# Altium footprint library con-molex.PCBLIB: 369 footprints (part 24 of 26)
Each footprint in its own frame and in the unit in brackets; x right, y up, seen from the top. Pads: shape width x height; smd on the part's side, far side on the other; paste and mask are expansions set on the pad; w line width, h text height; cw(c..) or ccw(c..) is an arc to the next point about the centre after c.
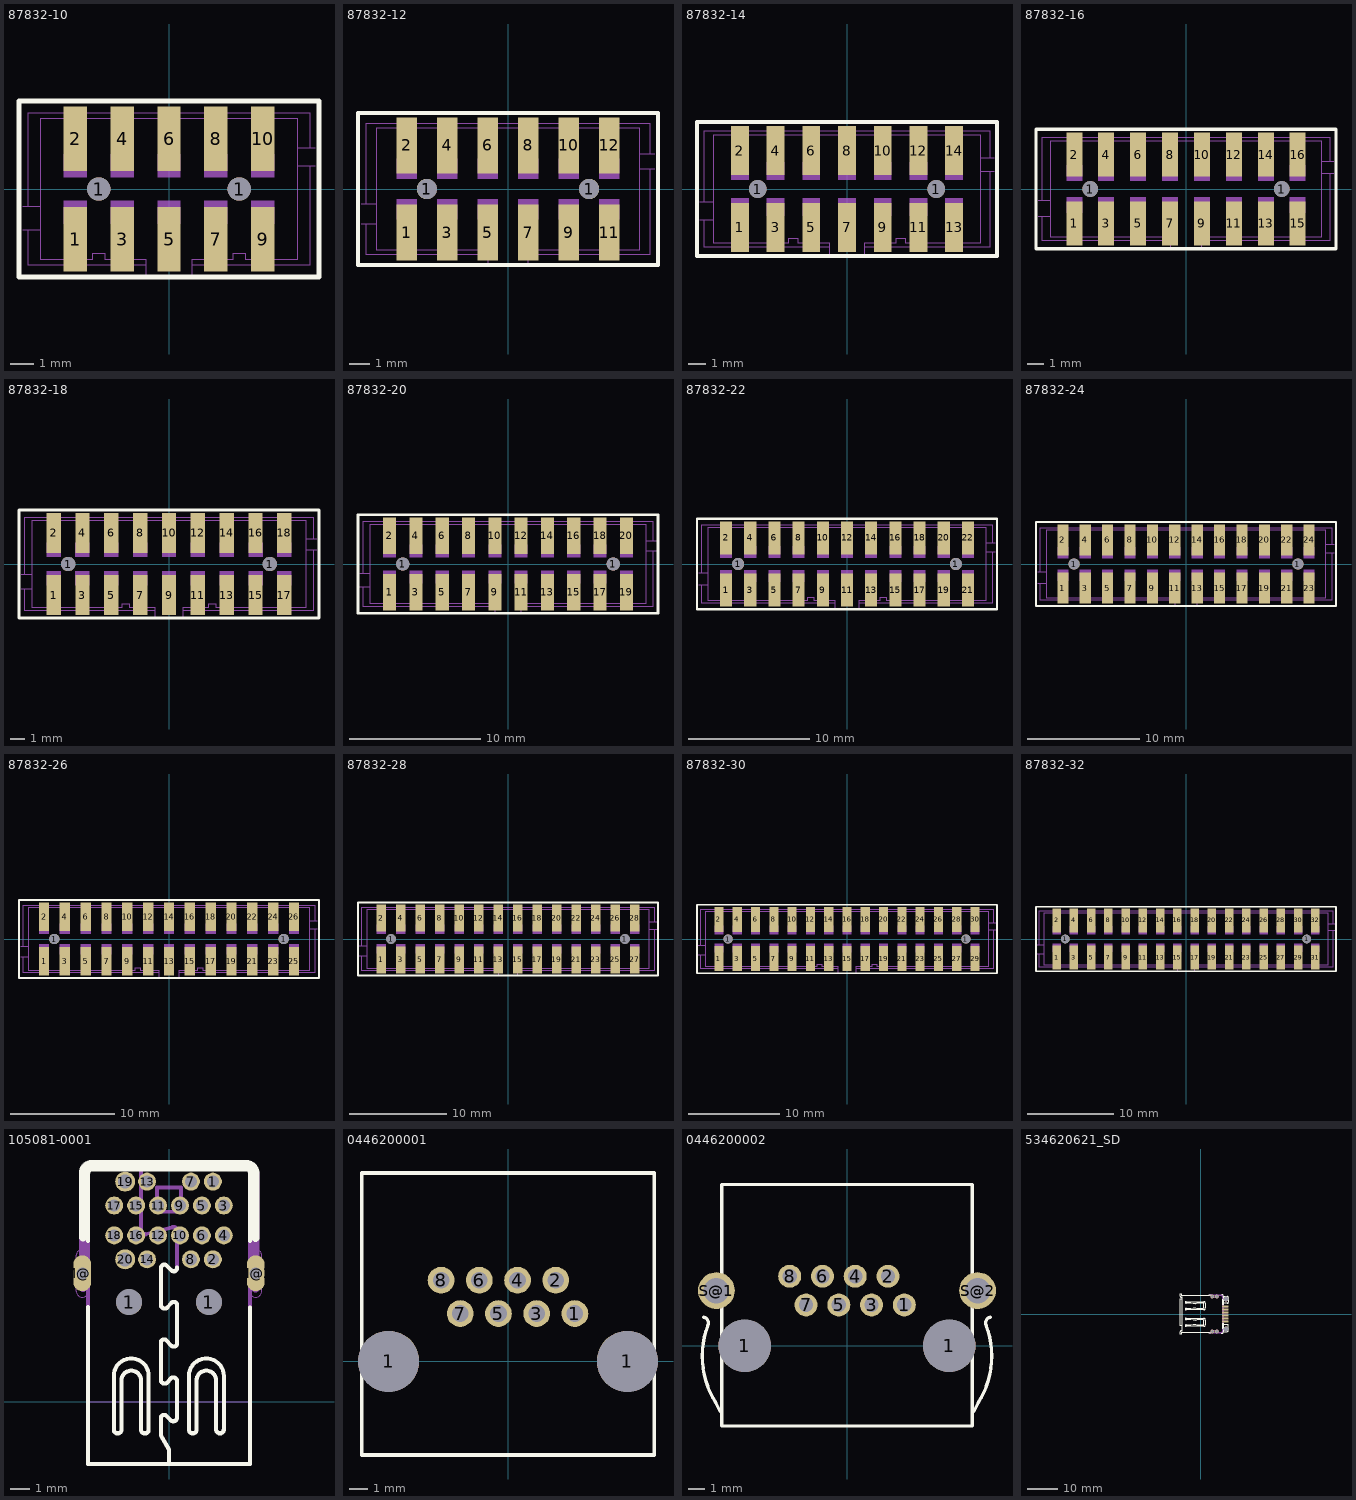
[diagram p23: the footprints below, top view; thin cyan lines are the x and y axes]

## 87832-10 [mm]
pads (12):
  rect 1x2.75 smd: 1(-4,-2.15) 2(-4,2.15) 3(-2,-2.15) 4(-2,2.15) 5(0,-2.15) 6(0,2.15) 7(2,-2.15) 8(2,2.15) 9(4,-2.15) 10(4,2.15)
  round 1 hole 1: 1(-3,0) 1(3,0)
Top Overlay:
  lines w0.203: -6.4,-3.75 6.4,-3.75 6.4,3.75 -6.4,3.75 -6.4,-3.75
Mechanical 16:
  rectangle: -4.5,0.5 -3.5,1.5
  rectangle: -2.5,0.5 -1.5,1.5
  rectangle: -0.5,0.5 0.5,1.5
  rectangle: 1.5,0.5 2.5,1.5
  rectangle: -4.5,-1.5 -3.5,-0.5
  rectangle: -2.5,-1.5 -1.5,-0.5
  rectangle: -0.5,-1.5 0.5,-0.5
  rectangle: 1.5,-1.5 2.5,-0.5
  rectangle: 3.5,0.5 4.5,1.5
  rectangle: 3.5,-1.5 4.5,-0.5
  lines w0.051: -6.25,-1.75 -6,-1.75 ; -6.25,-0.75 -6,-0.75 ; -1,-3.75 -1,-3.25 ; 1,-3.75 1,-3.25 ; 6.25,1 6,1 ; 6.25,1.75 6,1.75 ; -6,-1.75 -5.5,-1.75 ; -6,-1.75 -6,-3.25 -1,-3.25 ; -6,-0.75 -5.5,-0.75 ; -6,-0.75 -6,3.25 6,3.25 6,1.75 ; -5.5,-1.75 -5.5,-0.75 ; -5.5,-1.75 -5.5,-3 -3.25,-3 -3.25,-2.75 -2.75,-2.75 -2.75,-3 -1,-3 -1,-3.25 ; -5.5,-0.75 -5.5,3 -4.25,3 -4.25,2.75 -3.75,2.75 -3.75,3 -2.25,3 -2.25,2.75 -1.75,2.75 -1.75,3 -0.25,3 -0.25,2.75 0.25,2.75 0.25,3 1.75,3 1.75,2.75 2.25,2.75 2.25,3 3.75,3 3.75,2.75 4.25,2.75 4.25,3 5.5,3 5.5,1.75 ; 1,-3.25 1,-3 2.75,-3 2.75,-2.75 3.25,-2.75 3.25,-3 5.5,-3 5.5,1 ; 1,-3.25 6,-3.25 6,1 ; 5.5,1 5.5,1.75 ; 5.5,1 6,1 ; 5.5,1.75 6,1.75
  text "1" at -5.25,-2.75 h0.94

## 87832-12 [mm]
pads (14):
  rect 1x2.75 smd: 1(-5,-2.15) 2(-5,2.15) 3(-3,-2.15) 4(-3,2.15) 5(-1,-2.15) 6(-1,2.15) 7(1,-2.15) 8(1,2.15) 9(3,-2.15) 10(3,2.15) 11(5,-2.15) 12(5,2.15)
  round 1 hole 1: 1(-4,0) 1(4,0)
Top Overlay:
  lines w0.203: -7.4,-3.75 7.4,-3.75 7.4,3.75 -7.4,3.75 -7.4,-3.75
Mechanical 16:
  rectangle: -5.5,0.5 -4.5,1.5
  rectangle: -3.5,0.5 -2.5,1.5
  rectangle: -1.5,0.5 -0.5,1.5
  rectangle: 0.5,0.5 1.5,1.5
  rectangle: -5.5,-1.5 -4.5,-0.5
  rectangle: -3.5,-1.5 -2.5,-0.5
  rectangle: -1.5,-1.5 -0.5,-0.5
  rectangle: 0.5,-1.5 1.5,-0.5
  rectangle: 2.5,0.5 3.5,1.5
  rectangle: 2.5,-1.5 3.5,-0.5
  rectangle: 4.5,0.5 5.5,1.5
  rectangle: 4.5,-1.5 5.5,-0.5
  lines w0.051: -7.25,-1.75 -7,-1.75 ; -7.25,-0.75 -7,-0.75 ; -1,-3.75 -1,-3.25 ; 1,-3.75 1,-3.25 ; 7.25,1 7,1 ; 7.25,1.75 7,1.75 ; -7,-1.75 -6.5,-1.75 ; -7,-1.75 -7,-3.25 -1,-3.25 ; -7,-0.75 -6.5,-0.75 ; -7,-0.75 -7,3.25 7,3.25 7,1.75 ; -6.5,-1.75 -6.5,-0.75 ; -6.5,-1.75 -6.5,-3 -3.25,-3 -3.25,-2.75 -2.75,-2.75 -2.75,-3 -1,-3 -1,-3.25 ; -6.5,-0.75 -6.5,3 -5.25,3 -5.25,2.75 -4.75,2.75 -4.75,3 -3.25,3 -3.25,2.75 -2.75,2.75 -2.75,3 -1.25,3 -1.25,2.75 -0.75,2.75 -0.75,3 0.75,3 0.75,2.75 1.25,2.75 1.25,3 2.75,3 2.75,2.75 3.25,2.75 3.25,3 4.75,3 4.75,2.75 5.25,2.75 5.25,3 6.5,3 6.5,1.75 ; 1,-3.25 1,-3 2.75,-3 2.75,-2.75 3.25,-2.75 3.25,-3 6.5,-3 6.5,1 ; 1,-3.25 7,-3.25 7,1 ; 6.5,1 6.5,1.75 ; 6.5,1 7,1 ; 6.5,1.75 7,1.75
  text "1" at -6.25,-2.75 h0.94

## 87832-14 [mm]
pads (16):
  rect 1x2.75 smd: 1(-6,-2.15) 2(-6,2.15) 3(-4,-2.15) 4(-4,2.15) 5(-2,-2.15) 6(-2,2.15) 7(0,-2.15) 8(0,2.15) 9(2,-2.15) 10(2,2.15) 11(4,-2.15) 12(4,2.15) 13(6,-2.15) 14(6,2.15)
  round 1 hole 1: 1(-5,0) 1(5,0)
Top Overlay:
  lines w0.203: -8.4,-3.75 8.4,-3.75 8.4,3.75 -8.4,3.75 -8.4,-3.75
Mechanical 16:
  rectangle: -6.5,0.5 -5.5,1.5
  rectangle: -4.5,0.5 -3.5,1.5
  rectangle: -2.5,0.5 -1.5,1.5
  rectangle: -0.5,0.5 0.5,1.5
  rectangle: -6.5,-1.5 -5.5,-0.5
  rectangle: -4.5,-1.5 -3.5,-0.5
  rectangle: -2.5,-1.5 -1.5,-0.5
  rectangle: -0.5,-1.5 0.5,-0.5
  rectangle: 1.5,0.5 2.5,1.5
  rectangle: 1.5,-1.5 2.5,-0.5
  rectangle: 3.5,0.5 4.5,1.5
  rectangle: 3.5,-1.5 4.5,-0.5
  rectangle: 5.5,0.5 6.5,1.5
  rectangle: 5.5,-1.5 6.5,-0.5
  lines w0.051: -8.25,-1.75 -8,-1.75 ; -8.25,-0.75 -8,-0.75 ; -1,-3.75 -1,-3.25 ; 1,-3.75 1,-3.25 ; 8.25,1 8,1 ; 8.25,1.75 8,1.75 ; -8,-1.75 -7.5,-1.75 ; -8,-1.75 -8,-3.25 -1,-3.25 ; -8,-0.75 -7.5,-0.75 ; -8,-0.75 -8,3.25 8,3.25 8,1.75 ; -7.5,-1.75 -7.5,-0.75 ; -7.5,-1.75 -7.5,-3 -3.25,-3 -3.25,-2.75 -2.75,-2.75 -2.75,-3 -1,-3 -1,-3.25 ; -7.5,-0.75 -7.5,3 -6.25,3 -6.25,2.75 -5.75,2.75 -5.75,3 -4.25,3 -4.25,2.75 -3.75,2.75 -3.75,3 -2.25,3 -2.25,2.75 -1.75,2.75 -1.75,3 -0.25,3 -0.25,2.75 0.25,2.75 0.25,3 1.75,3 1.75,2.75 2.25,2.75 2.25,3 3.75,3 3.75,2.75 4.25,2.75 4.25,3 5.75,3 5.75,2.75 6.25,2.75 6.25,3 7.5,3 7.5,1.75 ; 1,-3.25 1,-3 2.75,-3 2.75,-2.75 3.25,-2.75 3.25,-3 7.5,-3 7.5,1 ; 1,-3.25 8,-3.25 8,1 ; 7.5,1 7.5,1.75 ; 7.5,1 8,1 ; 7.5,1.75 8,1.75
  text "1" at -7.25,-2.75 h0.94

## 87832-16 [mm]
pads (18):
  rect 1x2.75 smd: 1(-7,-2.15) 2(-7,2.15) 3(-5,-2.15) 4(-5,2.15) 5(-3,-2.15) 6(-3,2.15) 7(-1,-2.15) 8(-1,2.15) 9(1,-2.15) 10(1,2.15) 11(3,-2.15) 12(3,2.15) 13(5,-2.15) 14(5,2.15) 15(7,-2.15) 16(7,2.15)
  round 1 hole 1: 1(-6,0) 1(6,0)
Top Overlay:
  lines w0.203: -9.4,-3.75 9.4,-3.75 9.4,3.75 -9.4,3.75 -9.4,-3.75
Mechanical 16:
  rectangle: -7.5,0.5 -6.5,1.5
  rectangle: -5.5,0.5 -4.5,1.5
  rectangle: -3.5,0.5 -2.5,1.5
  rectangle: -1.5,0.5 -0.5,1.5
  rectangle: -7.5,-1.5 -6.5,-0.5
  rectangle: -5.5,-1.5 -4.5,-0.5
  rectangle: -3.5,-1.5 -2.5,-0.5
  rectangle: -1.5,-1.5 -0.5,-0.5
  rectangle: 0.5,0.5 1.5,1.5
  rectangle: 0.5,-1.5 1.5,-0.5
  rectangle: 2.5,0.5 3.5,1.5
  rectangle: 2.5,-1.5 3.5,-0.5
  rectangle: 4.5,0.5 5.5,1.5
  rectangle: 4.5,-1.5 5.5,-0.5
  rectangle: 6.5,0.5 7.5,1.5
  rectangle: 6.5,-1.5 7.5,-0.5
  lines w0.051: -9.25,-1.75 -9,-1.75 ; -9.25,-0.75 -9,-0.75 ; -1,-3.75 -1,-3.25 ; 1,-3.75 1,-3.25 ; 9.25,1 9,1 ; 9.25,1.75 9,1.75 ; -9,-1.75 -8.5,-1.75 ; -9,-1.75 -9,-3.25 -1,-3.25 ; -9,-0.75 -8.5,-0.75 ; -9,-0.75 -9,3.25 9,3.25 9,1.75 ; -8.5,-1.75 -8.5,-0.75 ; -8.5,-1.75 -8.5,-3 -3.25,-3 -3.25,-2.75 -2.75,-2.75 -2.75,-3 -1,-3 -1,-3.25 ; -8.5,-0.75 -8.5,3 -7.25,3 -7.25,2.75 -6.75,2.75 -6.75,3 -5.25,3 -5.25,2.75 -4.75,2.75 -4.75,3 -3.25,3 -3.25,2.75 -2.75,2.75 -2.75,3 -1.25,3 -1.25,2.75 -0.75,2.75 -0.75,3 0.75,3 0.75,2.75 1.25,2.75 1.25,3 2.75,3 2.75,2.75 3.25,2.75 3.25,3 4.75,3 4.75,2.75 5.25,2.75 5.25,3 6.75,3 6.75,2.75 7.25,2.75 7.25,3 8.5,3 8.5,1.75 ; 1,-3.25 1,-3 2.75,-3 2.75,-2.75 3.25,-2.75 3.25,-3 8.5,-3 8.5,1 ; 1,-3.25 9,-3.25 9,1 ; 8.5,1 8.5,1.75 ; 8.5,1 9,1 ; 8.5,1.75 9,1.75
  text "1" at -8.25,-2.75 h0.94

## 87832-18 [mm]
pads (20):
  rect 1x2.75 smd: 1(-8,-2.15) 2(-8,2.15) 3(-6,-2.15) 4(-6,2.15) 5(-4,-2.15) 6(-4,2.15) 7(-2,-2.15) 8(-2,2.15) 9(0,-2.15) 10(0,2.15) 11(2,-2.15) 12(2,2.15) 13(4,-2.15) 14(4,2.15) 15(6,-2.15) 16(6,2.15) 17(8,-2.15) 18(8,2.15)
  round 1 hole 1: 1(-7,0) 1(7,0)
Top Overlay:
  lines w0.203: -10.4,-3.75 10.4,-3.75 10.4,3.75 -10.4,3.75 -10.4,-3.75
Mechanical 16:
  rectangle: -8.5,0.5 -7.5,1.5
  rectangle: -6.5,0.5 -5.5,1.5
  rectangle: -4.5,0.5 -3.5,1.5
  rectangle: -2.5,0.5 -1.5,1.5
  rectangle: -8.5,-1.5 -7.5,-0.5
  rectangle: -6.5,-1.5 -5.5,-0.5
  rectangle: -4.5,-1.5 -3.5,-0.5
  rectangle: -2.5,-1.5 -1.5,-0.5
  rectangle: -0.5,0.5 0.5,1.5
  rectangle: -0.5,-1.5 0.5,-0.5
  rectangle: 1.5,0.5 2.5,1.5
  rectangle: 1.5,-1.5 2.5,-0.5
  rectangle: 3.5,0.5 4.5,1.5
  rectangle: 3.5,-1.5 4.5,-0.5
  rectangle: 5.5,0.5 6.5,1.5
  rectangle: 5.5,-1.5 6.5,-0.5
  rectangle: 7.5,0.5 8.5,1.5
  rectangle: 7.5,-1.5 8.5,-0.5
  lines w0.051: -10.25,-1.75 -10,-1.75 ; -10.25,-0.75 -10,-0.75 ; -1,-3.75 -1,-3.25 ; 1,-3.75 1,-3.25 ; 10.25,1 10,1 ; 10.25,1.75 10,1.75 ; -10,-1.75 -9.5,-1.75 ; -10,-1.75 -10,-3.25 -1,-3.25 ; -10,-0.75 -9.5,-0.75 ; -10,-0.75 -10,3.25 10,3.25 10,1.75 ; -9.5,-1.75 -9.5,-0.75 ; -9.5,-1.75 -9.5,-3 -3.25,-3 -3.25,-2.75 -2.75,-2.75 -2.75,-3 -1,-3 -1,-3.25 ; -9.5,-0.75 -9.5,3 -8.25,3 -8.25,2.75 -7.75,2.75 -7.75,3 -6.25,3 -6.25,2.75 -5.75,2.75 -5.75,3 -4.25,3 -4.25,2.75 -3.75,2.75 -3.75,3 -2.25,3 -2.25,2.75 -1.75,2.75 -1.75,3 -0.25,3 -0.25,2.75 0.25,2.75 0.25,3 1.75,3 1.75,2.75 2.25,2.75 2.25,3 3.75,3 3.75,2.75 4.25,2.75 4.25,3 5.75,3 5.75,2.75 6.25,2.75 6.25,3 7.75,3 7.75,2.75 8.25,2.75 8.25,3 9.5,3 9.5,1.75 ; 1,-3.25 1,-3 2.75,-3 2.75,-2.75 3.25,-2.75 3.25,-3 9.5,-3 9.5,1 ; 1,-3.25 10,-3.25 10,1 ; 9.5,1 9.5,1.75 ; 9.5,1 10,1 ; 9.5,1.75 10,1.75
  text "1" at -9.25,-2.75 h0.94

## 87832-20 [mm]
pads (22):
  rect 1x2.75 smd: 1(-9,-2.15) 2(-9,2.15) 3(-7,-2.15) 4(-7,2.15) 5(-5,-2.15) 6(-5,2.15) 7(-3,-2.15) 8(-3,2.15) 9(-1,-2.15) 10(-1,2.15) 11(1,-2.15) 12(1,2.15) 13(3,-2.15) 14(3,2.15) 15(5,-2.15) 16(5,2.15) 17(7,-2.15) 18(7,2.15) 19(9,-2.15) 20(9,2.15)
  round 1 hole 1: 1(-8,0) 1(8,0)
Top Overlay:
  lines w0.203: -11.4,-3.75 11.4,-3.75 11.4,3.75 -11.4,3.75 -11.4,-3.75
Mechanical 16:
  rectangle: -9.5,0.5 -8.5,1.5
  rectangle: -7.5,0.5 -6.5,1.5
  rectangle: -5.5,0.5 -4.5,1.5
  rectangle: -3.5,0.5 -2.5,1.5
  rectangle: -9.5,-1.5 -8.5,-0.5
  rectangle: -7.5,-1.5 -6.5,-0.5
  rectangle: -5.5,-1.5 -4.5,-0.5
  rectangle: -3.5,-1.5 -2.5,-0.5
  rectangle: -1.5,0.5 -0.5,1.5
  rectangle: -1.5,-1.5 -0.5,-0.5
  rectangle: 0.5,0.5 1.5,1.5
  rectangle: 0.5,-1.5 1.5,-0.5
  rectangle: 2.5,0.5 3.5,1.5
  rectangle: 2.5,-1.5 3.5,-0.5
  rectangle: 4.5,0.5 5.5,1.5
  rectangle: 4.5,-1.5 5.5,-0.5
  rectangle: 6.5,0.5 7.5,1.5
  rectangle: 6.5,-1.5 7.5,-0.5
  rectangle: 8.5,0.5 9.5,1.5
  rectangle: 8.5,-1.5 9.5,-0.5
  lines w0.051: -11.25,-1.75 -11,-1.75 ; -11.25,-0.75 -11,-0.75 ; -1,-3.75 -1,-3.25 ; 1,-3.75 1,-3.25 ; 11.25,1 11,1 ; 11.25,1.75 11,1.75 ; -11,-1.75 -10.5,-1.75 ; -11,-1.75 -11,-3.25 -1,-3.25 ; -11,-0.75 -10.5,-0.75 ; -11,-0.75 -11,3.25 11,3.25 11,1.75 ; -10.5,-1.75 -10.5,-0.75 ; -10.5,-1.75 -10.5,-3 -3.25,-3 -3.25,-2.75 -2.75,-2.75 -2.75,-3 -1,-3 -1,-3.25 ; -10.5,-0.75 -10.5,3 -9.25,3 -9.25,2.75 -8.75,2.75 -8.75,3 -7.25,3 -7.25,2.75 -6.75,2.75 -6.75,3 -5.25,3 -5.25,2.75 -4.75,2.75 -4.75,3 -3.25,3 -3.25,2.75 -2.75,2.75 -2.75,3 -1.25,3 -1.25,2.75 -0.75,2.75 -0.75,3 0.75,3 0.75,2.75 1.25,2.75 1.25,3 2.75,3 2.75,2.75 3.25,2.75 3.25,3 4.75,3 4.75,2.75 5.25,2.75 5.25,3 6.75,3 6.75,2.75 7.25,2.75 7.25,3 8.75,3 8.75,2.75 9.25,2.75 9.25,3 10.5,3 10.5,1.75 ; 1,-3.25 1,-3 2.75,-3 2.75,-2.75 3.25,-2.75 3.25,-3 10.5,-3 10.5,1 ; 1,-3.25 11,-3.25 11,1 ; 10.5,1 10.5,1.75 ; 10.5,1 11,1 ; 10.5,1.75 11,1.75
  text "1" at -10.25,-2.75 h0.94

## 87832-22 [mm]
pads (24):
  rect 1x2.75 smd: 1(-10,-2.15) 2(-10,2.15) 3(-8,-2.15) 4(-8,2.15) 5(-6,-2.15) 6(-6,2.15) 7(-4,-2.15) 8(-4,2.15) 9(-2,-2.15) 10(-2,2.15) 11(0,-2.15) 12(0,2.15) 13(2,-2.15) 14(2,2.15) 15(4,-2.15) 16(4,2.15) 17(6,-2.15) 18(6,2.15) 19(8,-2.15) 20(8,2.15) 21(10,-2.15) 22(10,2.15)
  round 1 hole 1: 1(-9,0) 1(9,0)
Top Overlay:
  lines w0.203: -12.4,-3.75 12.4,-3.75 12.4,3.75 -12.4,3.75 -12.4,-3.75
Mechanical 16:
  rectangle: -10.5,0.5 -9.5,1.5
  rectangle: -8.5,0.5 -7.5,1.5
  rectangle: -6.5,0.5 -5.5,1.5
  rectangle: -4.5,0.5 -3.5,1.5
  rectangle: -10.5,-1.5 -9.5,-0.5
  rectangle: -8.5,-1.5 -7.5,-0.5
  rectangle: -6.5,-1.5 -5.5,-0.5
  rectangle: -4.5,-1.5 -3.5,-0.5
  rectangle: -2.5,0.5 -1.5,1.5
  rectangle: -2.5,-1.5 -1.5,-0.5
  rectangle: -0.5,0.5 0.5,1.5
  rectangle: -0.5,-1.5 0.5,-0.5
  rectangle: 1.5,0.5 2.5,1.5
  rectangle: 1.5,-1.5 2.5,-0.5
  rectangle: 3.5,0.5 4.5,1.5
  rectangle: 3.5,-1.5 4.5,-0.5
  rectangle: 5.5,0.5 6.5,1.5
  rectangle: 5.5,-1.5 6.5,-0.5
  rectangle: 7.5,0.5 8.5,1.5
  rectangle: 7.5,-1.5 8.5,-0.5
  rectangle: 9.5,0.5 10.5,1.5
  rectangle: 9.5,-1.5 10.5,-0.5
  lines w0.051: -12.25,-1.75 -12,-1.75 ; -12.25,-0.75 -12,-0.75 ; -1,-3.75 -1,-3.25 ; 1,-3.75 1,-3.25 ; 12.25,1 12,1 ; 12.25,1.75 12,1.75 ; -12,-1.75 -11.5,-1.75 ; -12,-1.75 -12,-3.25 -1,-3.25 ; -12,-0.75 -11.5,-0.75 ; -12,-0.75 -12,3.25 12,3.25 12,1.75 ; -11.5,-1.75 -11.5,-0.75 ; -11.5,-1.75 -11.5,-3 -3.25,-3 -3.25,-2.75 -2.75,-2.75 -2.75,-3 -1,-3 -1,-3.25 ; -11.5,-0.75 -11.5,3 -10.25,3 -10.25,2.75 -9.75,2.75 -9.75,3 -8.25,3 -8.25,2.75 -7.75,2.75 -7.75,3 -6.25,3 -6.25,2.75 -5.75,2.75 -5.75,3 -4.25,3 -4.25,2.75 -3.75,2.75 -3.75,3 -2.25,3 -2.25,2.75 -1.75,2.75 -1.75,3 -0.25,3 -0.25,2.75 0.25,2.75 0.25,3 1.75,3 1.75,2.75 2.25,2.75 2.25,3 3.75,3 3.75,2.75 4.25,2.75 4.25,3 5.75,3 5.75,2.75 6.25,2.75 6.25,3 7.75,3 7.75,2.75 8.25,2.75 8.25,3 9.75,3 9.75,2.75 10.25,2.75 10.25,3 11.5,3 11.5,1.75 ; 1,-3.25 1,-3 2.75,-3 2.75,-2.75 3.25,-2.75 3.25,-3 11.5,-3 11.5,1 ; 1,-3.25 12,-3.25 12,1 ; 11.5,1 11.5,1.75 ; 11.5,1 12,1 ; 11.5,1.75 12,1.75
  text "1" at -11.25,-2.75 h0.94

## 87832-24 [mm]
pads (26):
  rect 1x2.75 smd: 1(-11,-2.15) 2(-11,2.15) 3(-9,-2.15) 4(-9,2.15) 5(-7,-2.15) 6(-7,2.15) 7(-5,-2.15) 8(-5,2.15) 9(-3,-2.15) 10(-3,2.15) 11(-1,-2.15) 12(-1,2.15) 13(1,-2.15) 14(1,2.15) 15(3,-2.15) 16(3,2.15) 17(5,-2.15) 18(5,2.15) 19(7,-2.15) 20(7,2.15) 21(9,-2.15) 22(9,2.15) 23(11,-2.15) 24(11,2.15)
  round 1 hole 1: 1(-10,0) 1(10,0)
Top Overlay:
  lines w0.203: -13.4,-3.75 13.4,-3.75 13.4,3.75 -13.4,3.75 -13.4,-3.75
Mechanical 16:
  rectangle: -11.5,0.5 -10.5,1.5
  rectangle: -9.5,0.5 -8.5,1.5
  rectangle: -7.5,0.5 -6.5,1.5
  rectangle: -5.5,0.5 -4.5,1.5
  rectangle: -11.5,-1.5 -10.5,-0.5
  rectangle: -9.5,-1.5 -8.5,-0.5
  rectangle: -7.5,-1.5 -6.5,-0.5
  rectangle: -5.5,-1.5 -4.5,-0.5
  rectangle: -3.5,0.5 -2.5,1.5
  rectangle: -3.5,-1.5 -2.5,-0.5
  rectangle: -1.5,0.5 -0.5,1.5
  rectangle: -1.5,-1.5 -0.5,-0.5
  rectangle: 0.5,0.5 1.5,1.5
  rectangle: 0.5,-1.5 1.5,-0.5
  rectangle: 2.5,0.5 3.5,1.5
  rectangle: 2.5,-1.5 3.5,-0.5
  rectangle: 4.5,0.5 5.5,1.5
  rectangle: 4.5,-1.5 5.5,-0.5
  rectangle: 6.5,0.5 7.5,1.5
  rectangle: 6.5,-1.5 7.5,-0.5
  rectangle: 8.5,0.5 9.5,1.5
  rectangle: 8.5,-1.5 9.5,-0.5
  rectangle: 10.5,0.5 11.5,1.5
  rectangle: 10.5,-1.5 11.5,-0.5
  lines w0.051: -13.25,-1.75 -13,-1.75 ; -13.25,-0.75 -13,-0.75 ; -1,-3.75 -1,-3.25 ; 1,-3.75 1,-3.25 ; 13.25,1 13,1 ; 13.25,1.75 13,1.75 ; -13,-1.75 -12.5,-1.75 ; -13,-1.75 -13,-3.25 -1,-3.25 ; -13,-0.75 -12.5,-0.75 ; -13,-0.75 -13,3.25 13,3.25 13,1.75 ; -12.5,-1.75 -12.5,-0.75 ; -12.5,-1.75 -12.5,-3 -3.25,-3 -3.25,-2.75 -2.75,-2.75 -2.75,-3 -1,-3 -1,-3.25 ; -12.5,-0.75 -12.5,3 -11.25,3 -11.25,2.75 -10.75,2.75 -10.75,3 -9.25,3 -9.25,2.75 -8.75,2.75 -8.75,3 -7.25,3 -7.25,2.75 -6.75,2.75 -6.75,3 -5.25,3 -5.25,2.75 -4.75,2.75 -4.75,3 -3.25,3 -3.25,2.75 -2.75,2.75 -2.75,3 -1.25,3 -1.25,2.75 -0.75,2.75 -0.75,3 0.75,3 0.75,2.75 1.25,2.75 1.25,3 2.75,3 2.75,2.75 3.25,2.75 3.25,3 4.75,3 4.75,2.75 5.25,2.75 5.25,3 6.75,3 6.75,2.75 7.25,2.75 7.25,3 8.75,3 8.75,2.75 9.25,2.75 9.25,3 10.75,3 10.75,2.75 11.25,2.75 11.25,3 12.5,3 12.5,1.75 ; 1,-3.25 1,-3 2.75,-3 2.75,-2.75 3.25,-2.75 3.25,-3 12.5,-3 12.5,1 ; 1,-3.25 13,-3.25 13,1 ; 12.5,1 12.5,1.75 ; 12.5,1 13,1 ; 12.5,1.75 13,1.75
  text "1" at -12.25,-2.75 h0.94

## 87832-26 [mm]
pads (28):
  rect 1x2.75 smd: 1(-12,-2.15) 2(-12,2.15) 3(-10,-2.15) 4(-10,2.15) 5(-8,-2.15) 6(-8,2.15) 7(-6,-2.15) 8(-6,2.15) 9(-4,-2.15) 10(-4,2.15) 11(-2,-2.15) 12(-2,2.15) 13(0,-2.15) 14(0,2.15) 15(2,-2.15) 16(2,2.15) 17(4,-2.15) 18(4,2.15) 19(6,-2.15) 20(6,2.15) 21(8,-2.15) 22(8,2.15) 23(10,-2.15) 24(10,2.15) 25(12,-2.15) 26(12,2.15)
  round 1 hole 1: 1(-11,0) 1(11,0)
Top Overlay:
  lines w0.203: -14.4,-3.75 14.4,-3.75 14.4,3.75 -14.4,3.75 -14.4,-3.75
Mechanical 16:
  rectangle: -12.5,0.5 -11.5,1.5
  rectangle: -10.5,0.5 -9.5,1.5
  rectangle: -8.5,0.5 -7.5,1.5
  rectangle: -6.5,0.5 -5.5,1.5
  rectangle: -12.5,-1.5 -11.5,-0.5
  rectangle: -10.5,-1.5 -9.5,-0.5
  rectangle: -8.5,-1.5 -7.5,-0.5
  rectangle: -6.5,-1.5 -5.5,-0.5
  rectangle: -4.5,0.5 -3.5,1.5
  rectangle: -4.5,-1.5 -3.5,-0.5
  rectangle: -2.5,0.5 -1.5,1.5
  rectangle: -2.5,-1.5 -1.5,-0.5
  rectangle: -0.5,0.5 0.5,1.5
  rectangle: -0.5,-1.5 0.5,-0.5
  rectangle: 1.5,0.5 2.5,1.5
  rectangle: 1.5,-1.5 2.5,-0.5
  rectangle: 3.5,0.5 4.5,1.5
  rectangle: 3.5,-1.5 4.5,-0.5
  rectangle: 5.5,0.5 6.5,1.5
  rectangle: 5.5,-1.5 6.5,-0.5
  rectangle: 7.5,0.5 8.5,1.5
  rectangle: 7.5,-1.5 8.5,-0.5
  rectangle: 9.5,0.5 10.5,1.5
  rectangle: 9.5,-1.5 10.5,-0.5
  rectangle: 11.5,0.5 12.5,1.5
  rectangle: 11.5,-1.5 12.5,-0.5
  lines w0.051: -14.25,-1.75 -14,-1.75 ; -14.25,-0.75 -14,-0.75 ; -1,-3.75 -1,-3.25 ; 1,-3.75 1,-3.25 ; 14.25,1 14,1 ; 14.25,1.75 14,1.75 ; -14,-1.75 -13.5,-1.75 ; -14,-1.75 -14,-3.25 -1,-3.25 ; -14,-0.75 -13.5,-0.75 ; -14,-0.75 -14,3.25 14,3.25 14,1.75 ; -13.5,-1.75 -13.5,-0.75 ; -13.5,-1.75 -13.5,-3 -3.25,-3 -3.25,-2.75 -2.75,-2.75 -2.75,-3 -1,-3 -1,-3.25 ; -13.5,-0.75 -13.5,3 -12.25,3 -12.25,2.75 -11.75,2.75 -11.75,3 -10.25,3 -10.25,2.75 -9.75,2.75 -9.75,3 -8.25,3 -8.25,2.75 -7.75,2.75 -7.75,3 -6.25,3 -6.25,2.75 -5.75,2.75 -5.75,3 -4.25,3 -4.25,2.75 -3.75,2.75 -3.75,3 -2.25,3 -2.25,2.75 -1.75,2.75 -1.75,3 -0.25,3 -0.25,2.75 0.25,2.75 0.25,3 1.75,3 1.75,2.75 2.25,2.75 2.25,3 3.75,3 3.75,2.75 4.25,2.75 4.25,3 5.75,3 5.75,2.75 6.25,2.75 6.25,3 7.75,3 7.75,2.75 8.25,2.75 8.25,3 9.75,3 9.75,2.75 10.25,2.75 10.25,3 11.75,3 11.75,2.75 12.25,2.75 12.25,3 13.5,3 13.5,1.75 ; 1,-3.25 1,-3 2.75,-3 2.75,-2.75 3.25,-2.75 3.25,-3 13.5,-3 13.5,1 ; 1,-3.25 14,-3.25 14,1 ; 13.5,1 13.5,1.75 ; 13.5,1 14,1 ; 13.5,1.75 14,1.75
  text "1" at -13.25,-2.75 h0.94

## 87832-28 [mm]
pads (30):
  rect 1x2.75 smd: 1(-13,-2.15) 2(-13,2.15) 3(-11,-2.15) 4(-11,2.15) 5(-9,-2.15) 6(-9,2.15) 7(-7,-2.15) 8(-7,2.15) 9(-5,-2.15) 10(-5,2.15) 11(-3,-2.15) 12(-3,2.15) 13(-1,-2.15) 14(-1,2.15) 15(1,-2.15) 16(1,2.15) 17(3,-2.15) 18(3,2.15) 19(5,-2.15) 20(5,2.15) 21(7,-2.15) 22(7,2.15) 23(9,-2.15) 24(9,2.15) 25(11,-2.15) 26(11,2.15) 27(13,-2.15) 28(13,2.15)
  round 1 hole 1: 1(-12,0) 1(12,0)
Top Overlay:
  lines w0.203: -15.4,-3.75 15.4,-3.75 15.4,3.75 -15.4,3.75 -15.4,-3.75
Mechanical 16:
  rectangle: -13.5,0.5 -12.5,1.5
  rectangle: -11.5,0.5 -10.5,1.5
  rectangle: -9.5,0.5 -8.5,1.5
  rectangle: -7.5,0.5 -6.5,1.5
  rectangle: -13.5,-1.5 -12.5,-0.5
  rectangle: -11.5,-1.5 -10.5,-0.5
  rectangle: -9.5,-1.5 -8.5,-0.5
  rectangle: -7.5,-1.5 -6.5,-0.5
  rectangle: -5.5,0.5 -4.5,1.5
  rectangle: -5.5,-1.5 -4.5,-0.5
  rectangle: -3.5,0.5 -2.5,1.5
  rectangle: -3.5,-1.5 -2.5,-0.5
  rectangle: -1.5,0.5 -0.5,1.5
  rectangle: -1.5,-1.5 -0.5,-0.5
  rectangle: 0.5,0.5 1.5,1.5
  rectangle: 0.5,-1.5 1.5,-0.5
  rectangle: 2.5,0.5 3.5,1.5
  rectangle: 2.5,-1.5 3.5,-0.5
  rectangle: 4.5,0.5 5.5,1.5
  rectangle: 4.5,-1.5 5.5,-0.5
  rectangle: 6.5,0.5 7.5,1.5
  rectangle: 6.5,-1.5 7.5,-0.5
  rectangle: 8.5,0.5 9.5,1.5
  rectangle: 8.5,-1.5 9.5,-0.5
  rectangle: 10.5,0.5 11.5,1.5
  rectangle: 10.5,-1.5 11.5,-0.5
  rectangle: 12.5,0.5 13.5,1.5
  rectangle: 12.5,-1.5 13.5,-0.5
  lines w0.051: -15.25,-1.75 -15,-1.75 ; -15.25,-0.75 -15,-0.75 ; -1,-3.75 -1,-3.25 ; 1,-3.75 1,-3.25 ; 15.25,1 15,1 ; 15.25,1.75 15,1.75 ; -15,-1.75 -14.5,-1.75 ; -15,-1.75 -15,-3.25 -1,-3.25 ; -15,-0.75 -14.5,-0.75 ; -15,-0.75 -15,3.25 15,3.25 15,1.75 ; -14.5,-1.75 -14.5,-0.75 ; -14.5,-1.75 -14.5,-3 -3.25,-3 -3.25,-2.75 -2.75,-2.75 -2.75,-3 -1,-3 -1,-3.25 ; -14.5,-0.75 -14.5,3 -13.25,3 -13.25,2.75 -12.75,2.75 -12.75,3 -11.25,3 -11.25,2.75 -10.75,2.75 -10.75,3 -9.25,3 -9.25,2.75 -8.75,2.75 -8.75,3 -7.25,3 -7.25,2.75 -6.75,2.75 -6.75,3 -5.25,3 -5.25,2.75 -4.75,2.75 -4.75,3 -3.25,3 -3.25,2.75 -2.75,2.75 -2.75,3 -1.25,3 -1.25,2.75 -0.75,2.75 -0.75,3 0.75,3 0.75,2.75 1.25,2.75 1.25,3 2.75,3 2.75,2.75 3.25,2.75 3.25,3 4.75,3 4.75,2.75 5.25,2.75 5.25,3 6.75,3 6.75,2.75 7.25,2.75 7.25,3 8.75,3 8.75,2.75 9.25,2.75 9.25,3 10.75,3 10.75,2.75 11.25,2.75 11.25,3 12.75,3 12.75,2.75 13.25,2.75 13.25,3 14.5,3 14.5,1.75 ; 1,-3.25 1,-3 2.75,-3 2.75,-2.75 3.25,-2.75 3.25,-3 14.5,-3 14.5,1 ; 1,-3.25 15,-3.25 15,1 ; 14.5,1 14.5,1.75 ; 14.5,1 15,1 ; 14.5,1.75 15,1.75
  text "1" at -14.25,-2.75 h0.94

## 87832-30 [mm]
pads (32):
  rect 1x2.75 smd: 1(-14,-2.15) 2(-14,2.15) 3(-12,-2.15) 4(-12,2.15) 5(-10,-2.15) 6(-10,2.15) 7(-8,-2.15) 8(-8,2.15) 9(-6,-2.15) 10(-6,2.15) 11(-4,-2.15) 12(-4,2.15) 13(-2,-2.15) 14(-2,2.15) 15(0,-2.15) 16(0,2.15) 17(2,-2.15) 18(2,2.15) 19(4,-2.15) 20(4,2.15) 21(6,-2.15) 22(6,2.15) 23(8,-2.15) 24(8,2.15) 25(10,-2.15) 26(10,2.15) 27(12,-2.15) 28(12,2.15) 29(14,-2.15) 30(14,2.15)
  round 1 hole 1: 1(-13,0) 1(13,0)
Top Overlay:
  lines w0.203: -16.4,-3.75 16.4,-3.75 16.4,3.75 -16.4,3.75 -16.4,-3.75
Mechanical 16:
  rectangle: -14.5,0.5 -13.5,1.5
  rectangle: -12.5,0.5 -11.5,1.5
  rectangle: -10.5,0.5 -9.5,1.5
  rectangle: -8.5,0.5 -7.5,1.5
  rectangle: -14.5,-1.5 -13.5,-0.5
  rectangle: -12.5,-1.5 -11.5,-0.5
  rectangle: -10.5,-1.5 -9.5,-0.5
  rectangle: -8.5,-1.5 -7.5,-0.5
  rectangle: -6.5,0.5 -5.5,1.5
  rectangle: -6.5,-1.5 -5.5,-0.5
  rectangle: -4.5,0.5 -3.5,1.5
  rectangle: -4.5,-1.5 -3.5,-0.5
  rectangle: -2.5,0.5 -1.5,1.5
  rectangle: -2.5,-1.5 -1.5,-0.5
  rectangle: -0.5,0.5 0.5,1.5
  rectangle: -0.5,-1.5 0.5,-0.5
  rectangle: 1.5,0.5 2.5,1.5
  rectangle: 1.5,-1.5 2.5,-0.5
  rectangle: 3.5,0.5 4.5,1.5
  rectangle: 3.5,-1.5 4.5,-0.5
  rectangle: 5.5,0.5 6.5,1.5
  rectangle: 5.5,-1.5 6.5,-0.5
  rectangle: 7.5,0.5 8.5,1.5
  rectangle: 7.5,-1.5 8.5,-0.5
  rectangle: 9.5,0.5 10.5,1.5
  rectangle: 9.5,-1.5 10.5,-0.5
  rectangle: 11.5,0.5 12.5,1.5
  rectangle: 11.5,-1.5 12.5,-0.5
  rectangle: 13.5,0.5 14.5,1.5
  rectangle: 13.5,-1.5 14.5,-0.5
  lines w0.051: -16.25,-1.75 -16,-1.75 ; -16.25,-0.75 -16,-0.75 ; -1,-3.75 -1,-3.25 ; 1,-3.75 1,-3.25 ; 16.25,1 16,1 ; 16.25,1.75 16,1.75 ; -16,-1.75 -15.5,-1.75 ; -16,-1.75 -16,-3.25 -1,-3.25 ; -16,-0.75 -15.5,-0.75 ; -16,-0.75 -16,3.25 16,3.25 16,1.75 ; -15.5,-1.75 -15.5,-0.75 ; -15.5,-1.75 -15.5,-3 -3.25,-3 -3.25,-2.75 -2.75,-2.75 -2.75,-3 -1,-3 -1,-3.25 ; -15.5,-0.75 -15.5,3 -14.25,3 -14.25,2.75 -13.75,2.75 -13.75,3 -12.25,3 -12.25,2.75 -11.75,2.75 -11.75,3 -10.25,3 -10.25,2.75 -9.75,2.75 -9.75,3 -8.25,3 -8.25,2.75 -7.75,2.75 -7.75,3 -6.25,3 -6.25,2.75 -5.75,2.75 -5.75,3 -4.25,3 -4.25,2.75 -3.75,2.75 -3.75,3 -2.25,3 -2.25,2.75 -1.75,2.75 -1.75,3 -0.25,3 -0.25,2.75 0.25,2.75 0.25,3 1.75,3 1.75,2.75 2.25,2.75 2.25,3 3.75,3 3.75,2.75 4.25,2.75 4.25,3 5.75,3 5.75,2.75 6.25,2.75 6.25,3 7.75,3 7.75,2.75 8.25,2.75 8.25,3 9.75,3 9.75,2.75 10.25,2.75 10.25,3 11.75,3 11.75,2.75 12.25,2.75 12.25,3 13.75,3 13.75,2.75 14.25,2.75 14.25,3 15.5,3 15.5,1.75 ; 1,-3.25 1,-3 2.75,-3 2.75,-2.75 3.25,-2.75 3.25,-3 15.5,-3 15.5,1 ; 1,-3.25 16,-3.25 16,1 ; 15.5,1 15.5,1.75 ; 15.5,1 16,1 ; 15.5,1.75 16,1.75
  text "1" at -15.25,-2.75 h0.94

## 87832-32 [mm]
pads (34):
  rect 1x2.75 smd: 1(-15,-2.15) 2(-15,2.15) 3(-13,-2.15) 4(-13,2.15) 5(-11,-2.15) 6(-11,2.15) 7(-9,-2.15) 8(-9,2.15) 9(-7,-2.15) 10(-7,2.15) 11(-5,-2.15) 12(-5,2.15) 13(-3,-2.15) 14(-3,2.15) 15(-1,-2.15) 16(-1,2.15) 17(1,-2.15) 18(1,2.15) 19(3,-2.15) 20(3,2.15) 21(5,-2.15) 22(5,2.15) 23(7,-2.15) 24(7,2.15) 25(9,-2.15) 26(9,2.15) 27(11,-2.15) 28(11,2.15) 29(13,-2.15) 30(13,2.15) 31(15,-2.15) 32(15,2.15)
  round 1 hole 1: 1(-14,0) 1(14,0)
Top Overlay:
  lines w0.203: -17.4,-3.75 17.4,-3.75 17.4,3.75 -17.4,3.75 -17.4,-3.75
Mechanical 16:
  rectangle: -15.5,0.5 -14.5,1.5
  rectangle: -13.5,0.5 -12.5,1.5
  rectangle: -11.5,0.5 -10.5,1.5
  rectangle: -9.5,0.5 -8.5,1.5
  rectangle: -15.5,-1.5 -14.5,-0.5
  rectangle: -13.5,-1.5 -12.5,-0.5
  rectangle: -11.5,-1.5 -10.5,-0.5
  rectangle: -9.5,-1.5 -8.5,-0.5
  rectangle: -7.5,0.5 -6.5,1.5
  rectangle: -7.5,-1.5 -6.5,-0.5
  rectangle: -5.5,0.5 -4.5,1.5
  rectangle: -5.5,-1.5 -4.5,-0.5
  rectangle: -3.5,0.5 -2.5,1.5
  rectangle: -3.5,-1.5 -2.5,-0.5
  rectangle: -1.5,0.5 -0.5,1.5
  rectangle: -1.5,-1.5 -0.5,-0.5
  rectangle: 0.5,0.5 1.5,1.5
  rectangle: 0.5,-1.5 1.5,-0.5
  rectangle: 2.5,0.5 3.5,1.5
  rectangle: 2.5,-1.5 3.5,-0.5
  rectangle: 4.5,0.5 5.5,1.5
  rectangle: 4.5,-1.5 5.5,-0.5
  rectangle: 6.5,0.5 7.5,1.5
  rectangle: 6.5,-1.5 7.5,-0.5
  rectangle: 8.5,0.5 9.5,1.5
  rectangle: 8.5,-1.5 9.5,-0.5
  rectangle: 10.5,0.5 11.5,1.5
  rectangle: 10.5,-1.5 11.5,-0.5
  rectangle: 12.5,0.5 13.5,1.5
  rectangle: 12.5,-1.5 13.5,-0.5
  rectangle: 14.5,0.5 15.5,1.5
  rectangle: 14.5,-1.5 15.5,-0.5
  lines w0.051: -17.25,-1.75 -17,-1.75 ; -17.25,-0.75 -17,-0.75 ; -1,-3.75 -1,-3.25 ; 1,-3.75 1,-3.25 ; 17.25,1 17,1 ; 17.25,1.75 17,1.75 ; -17,-1.75 -16.5,-1.75 ; -17,-1.75 -17,-3.25 -1,-3.25 ; -17,-0.75 -16.5,-0.75 ; -17,-0.75 -17,3.25 17,3.25 17,1.75 ; -16.5,-1.75 -16.5,-0.75 ; -16.5,-1.75 -16.5,-3 -3.25,-3 -3.25,-2.75 -2.75,-2.75 -2.75,-3 -1,-3 -1,-3.25 ; -16.5,-0.75 -16.5,3 -15.25,3 -15.25,2.75 -14.75,2.75 -14.75,3 -13.25,3 -13.25,2.75 -12.75,2.75 -12.75,3 -11.25,3 -11.25,2.75 -10.75,2.75 -10.75,3 -9.25,3 -9.25,2.75 -8.75,2.75 -8.75,3 -7.25,3 -7.25,2.75 -6.75,2.75 -6.75,3 -5.25,3 -5.25,2.75 -4.75,2.75 -4.75,3 -3.25,3 -3.25,2.75 -2.75,2.75 -2.75,3 -1.25,3 -1.25,2.75 -0.75,2.75 -0.75,3 0.75,3 0.75,2.75 1.25,2.75 1.25,3 2.75,3 2.75,2.75 3.25,2.75 3.25,3 4.75,3 4.75,2.75 5.25,2.75 5.25,3 6.75,3 6.75,2.75 7.25,2.75 7.25,3 8.75,3 8.75,2.75 9.25,2.75 9.25,3 10.75,3 10.75,2.75 11.25,2.75 11.25,3 12.75,3 12.75,2.75 13.25,2.75 13.25,3 14.75,3 14.75,2.75 15.25,2.75 15.25,3 16.5,3 16.5,1.75 ; 1,-3.25 1,-3 2.75,-3 2.75,-2.75 3.25,-2.75 3.25,-3 16.5,-3 16.5,1 ; 1,-3.25 17,-3.25 17,1 ; 16.5,1 16.5,1.75 ; 16.5,1 17,1 ; 16.5,1.75 17,1.75
  text "1" at -16.25,-2.75 h0.94

## 105081-0001 [mm]
pads (24):
  round 1.3 hole 1.3: 1(-2,5) 1(2,5)
  round 0.9 hole 0.6: 1(2.2,11.05) 2(2.2,7.15) 3(2.75,9.85) 4(2.75,8.35) 5(1.65,9.85) 6(1.65,8.35) 7(1.1,11.05) 8(1.1,7.15) 9(0.55,9.85) 10(0.55,8.35) 11(-0.55,9.85) 12(-0.55,8.35) 13(-1.1,11.05) 14(-1.1,7.15) 15(-1.65,9.85) 16(-1.65,8.35) 17(-2.75,9.85) 18(-2.75,8.35)
  round 1 hole 0.7: 19(-2.2,11.05) 20(-2.2,7.15)
  oval 0.9x1.8 hole 0.6: M@1(-4.35,6.45) M@2(4.35,6.45)
Top Overlay:
  lines w0.203: -4.052,4.753 -4.052,-3.115 4.072,-3.115 4.072,4.733 ; -4.052,8.061 -4.052,11.484 cw(c-3.869,11.484) -3.869,11.667 3.869,11.667 cw(c3.869,11.464) 4.072,11.464 4.072,8.061 ; 0,-3.014 0,-2.383 -0.407,-1.67 -0.407,-0.815 cw(c-0.246,-0.815) -0.122,-0.713 0.081,-0.916 ccw(c0.216,-0.781) 0.407,-0.774 0.407,1.039 ccw(c0.219,1.039) 0.061,1.14 -0.081,0.977 cw(c-0.222,1.1) -0.407,1.12 -0.407,2.973 cw(c-0.246,2.973) -0.122,3.075 0.102,2.83 ccw(c0.232,2.95) 0.407,2.973 0.407,4.846 ccw(c0.238,4.846) 0.102,4.948 -0.081,4.744 cw(c-0.221,4.87) -0.407,4.887 -0.407,6.72 cw(c-0.239,6.719) -0.122,6.841 0.122,6.597 ccw(c0.241,6.716) 0.407,6.74 ; -2.769,-1.385 ccw(c-2.576,-1.385) -2.383,-1.385 -2.383,1.079 cw(c-1.894,1.079) -1.405,1.079 -1.405,-1.385 ccw(c-1.212,-1.385) -1.018,-1.385 -1.018,1.303 ccw(c-1.894,1.303) -2.769,1.303 -2.769,-1.385 ; 0.998,-1.385 ccw(c1.191,-1.385) 1.385,-1.385 1.385,1.079 cw(c1.873,1.079) 2.362,1.079 2.362,-1.385 ccw(c2.555,-1.385) 2.749,-1.385 2.749,1.303 ccw(c1.873,1.303) 0.998,1.303 0.998,-1.385
  lines w0.4: -4.317,8.241 -4.317,11.484 cw(c-3.869,11.484) -3.869,11.932 3.869,11.932 cw(c3.869,11.464) 4.337,11.464 4.337,8.221
Mechanical 1:
  lines w0: -4.095,0 4.095,0
Mechanical 11:
  lines w0: -4.65,5.55 ccw(c-4.35,5.55) -4.35,5.25 ccw(c-4.35,5.55) -4.05,5.55 -4.05,7.35 ccw(c-4.35,7.35) -4.35,7.65 ccw(c-4.35,7.35) -4.65,7.35 -4.65,5.55 ; 4.05,5.55 ccw(c4.35,5.55) 4.35,5.25 ccw(c4.35,5.55) 4.65,5.55 4.65,7.35 ccw(c4.35,7.35) 4.35,7.65 ccw(c4.35,7.35) 4.05,7.35 4.05,5.55
Mechanical 16:
  lines w0.203: -4.052,-3.115 -4.052,11.484 ; -1.405,11.586 -1.405,8.593 ccw(c-1.226,8.583) -1.181,8.409 0.142,8.756 cw(c0.211,8.572) 0.407,8.573 0.407,6.74 ; 4.072,-3.115 4.072,11.464 ; -0.611,9.529 0.611,9.55 0.611,10.751 -0.611,10.751 -0.611,9.529
  lines w0.4: -4.317,5.701 -4.317,11.484 ; 4.337,5.681 4.337,11.464

## 0446200001 [mil]
pads (10):
  round 128 hole 128: 1(-250,0) 1(250,0)
  round 56 hole 35: 1(140,100) 2(100,170) 3(60,100) 4(20,170) 5(-20,100) 6(-60,170) 7(-100,100) 8(-140,170)
Top Overlay:
  lines w8: -306.1,-195.87 306.1,-195.87 306.1,394.13 -306.1,394.13 -306.1,-195.87

## 0446200002 [mil]
pads (12):
  round 128 hole 128: 1(-250,0) 1(250,0)
  round 56 hole 35: 1(140,100) 2(100,170) 3(60,100) 4(20,170) 5(-20,100) 6(-60,170) 7(-100,100) 8(-140,170)
  round 90 hole 62: S@1(-319,135) S@2(319,135)
Top Overlay:
  lines w8: -350,70 cw(c-352.5,56.25) -340,50 ccw(c-140,-25) -320,-140 -310,-160 ; 310,-160 320,-140 ccw(c140,-25) 340,50 cw(c352.5,56.25) 350,70 ; -306.1,-195.87 306.1,-195.87 306.1,394.13 -306.1,394.13 -306.1,-195.87

## 534620621_SD [mm]
pads (12):
  rect 2.2x0.7 smd: 1(8.25,2.5) 2(8.25,1.5) 3(8.25,0.5) 4(8.25,-0.5) 5(8.25,-1.5) 6(8.25,-2.5)
  round 1.6 hole 1.6: 1(8.45,-5) 1(8.45,5)
  round 1.27 hole 1: M1(3.9,5.85) M2(5.4,5.85) M3(3.9,-5.85) M4(5.4,-5.85)
Top Overlay:
  lines w0.102: -6.395,-3.837 -6.395,5.009 ; 3.428,-6.501 2.878,-6.501 2.878,-6.182 -6.501,-6.182 -6.501,-6.714 -6.821,-6.714 -6.821,-5.968 cw(c-6.501,-5.968) -6.501,-5.649 -6.182,-5.649 -6.182,-3.943 -6.821,-3.943 -6.821,5.116 -6.182,5.116 -6.182,5.649 -6.501,5.649 cw(c-6.501,5.968) -6.821,5.968 -6.821,6.714 -6.501,6.714 -6.501,6.182 2.878,6.182 2.878,6.501 3.534,6.501 ; 6.928,-6.501 ccw(c6.927,-5.862) 7.567,-5.862 ; 7.034,6.501 cw(c7.034,5.968) 7.567,5.968 7.567,3.138 ; 7.141,-4.862 7.141,-3.031 ; 7.141,3.138 7.141,4.968 ; 7.567,-3.031 7.567,-5.862 ; 7.674,-3.517 8.846,-3.517 cw(c8.846,-3.943) 9.273,-3.943 9.273,-5.436 cw(c8.846,-5.435) 8.846,-5.862 7.567,-5.862 ; 7.674,3.517 8.846,3.517 ccw(c8.846,3.943) 9.273,3.943 9.273,5.436 ccw(c8.846,5.435) 8.846,5.862 7.674,5.862 ; -4.903,-4.157 0.959,-4.157 ccw(c0.959,-3.517) 1.599,-3.517 1.599,-2.025 ccw(c0.959,-2.025) 0.959,-1.386 -4.903,-1.386 ccw(c-4.903,-1.652) -4.903,-1.918 cw(c-4.902,-26.003) -1.705,-2.132 -1.386,-1.918 0.746,-1.918 cw(c0.746,-2.238) 1.066,-2.238 1.066,-3.304 cw(c0.746,-3.304) 0.746,-3.624 -1.386,-3.624 -1.705,-3.41 cw(c-4.904,20.46) -4.903,-3.624 ccw(c-4.903,-3.89) -4.903,-4.157 ; -4.903,1.386 0.959,1.386 ccw(c0.959,2.025) 1.599,2.025 1.599,3.517 ccw(c0.959,3.517) 0.959,4.157 -4.903,4.157 ccw(c-4.903,3.89) -4.903,3.624 cw(c-4.904,-20.46) -1.705,3.41 -1.386,3.624 0.746,3.624 cw(c0.746,3.304) 1.066,3.304 1.066,2.238 cw(c0.746,2.238) 0.746,1.918 -1.386,1.918 -1.705,2.132 cw(c-4.902,26.003) -4.903,1.918 ccw(c-4.903,1.652) -4.903,1.386
Mechanical 11:
  lines w0: 3.4,-5.85 cw(c3.9,-5.85) 3.9,-5.35 5.4,-5.35 cw(c5.4,-5.85) 5.9,-5.85 cw(c5.4,-5.85) 5.4,-6.35 3.9,-6.35 cw(c3.9,-5.85) 3.4,-5.85 ; 3.4,5.85 cw(c3.9,5.85) 3.9,6.35 5.4,6.35 cw(c5.4,5.85) 5.9,5.85 cw(c5.4,5.85) 5.4,5.35 3.9,5.35 cw(c3.9,5.85) 3.4,5.85
Mechanical 16:
  rectangle: 7.15,2.25 9.05,2.75
  rectangle: 7.15,1.25 9.05,1.75
  rectangle: 7.15,0.25 9.05,0.75
  rectangle: 7.15,-0.75 9.05,-0.25
  rectangle: 7.15,-1.75 9.05,-1.25
  rectangle: 7.15,-2.75 9.05,-2.25
  lines w0.102: 2.878,-6.501 6.928,-6.501 ; 2.878,-6.182 6.821,-6.182 ccw(c6.821,-5.862) 7.141,-5.862 7.141,5.968 ccw(c6.928,5.968) 6.928,6.182 2.878,6.182 ; 2.878,6.501 7.034,6.501 ; 7.567,-5.862 7.567,5.968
